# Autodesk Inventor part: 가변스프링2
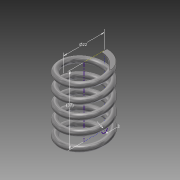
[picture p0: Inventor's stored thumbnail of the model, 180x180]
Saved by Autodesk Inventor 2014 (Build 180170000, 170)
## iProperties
Created: 2015-02
Part Number: 가변스프링2
Material: 강철, 탄소
Document SubType Name: Modeling
Designer: basic
Density: 7.87 g/cm^3
Appearance: 반연마
Mass: 18.6318 g
Surface Area: 32.4192 cm^2
Volume: 2.36745 cm^3
Author: basic
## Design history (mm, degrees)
sketch "스케치1"
  geometry: L1 (0, 0)-(11, 0); L2 (11, 0)-(11, 25.358); L3 (11, 25.358)-(0, 25.358); L4 (0, 25.358)-(0, 0); C1 r 1.5 at (11, 0)
  constraints: 8 end point, 2 parallel, 1 centre point, 1 coincident, 1 horizontal, 1 perpendicular
  dimensions: "d0" = 22 diameter of L2 L4; "d1" = 25.3583 distance of L3.end L1.start (derived); "d2" = 3 diameter of C1
feature "코일1" sketch "스케치1" pitch "d3" = 10; turns "d5" = 5; dims "d4" = 25.3583 (= d1), "d6" = 0, angle "d7" = 90 deg, angle "d8" = 90 deg, "d9" = 0, "d10" = 0
sketch "스케치2"
  geometry: L1 (0, 12.5)-(0, 9.5) reference; L2 (0, 12.5)-(0, 9.5) reference; 1 further point
  constraints: 2 vertical alignment
extrude "돌출1" cut sketch "스케치2" stored distance "d11" = 10; taper "d12" = 0 deg
node "작업 평면1"
sketch "스케치3"
  geometry: L1 (1.5, 0)-(-1.5, 0) reference; 1 further point
  constraints: 1 horizontal alignment
extrude "돌출2" cut sketch "스케치3" stored distance "d14" = 10; taper "d15" = 0 deg
node "솔리드1"
node "절단 모서리 투영1"
node "절단 모서리 투영2"
node "절단 모서리 투영3"
other parameters: "d13" = 0
